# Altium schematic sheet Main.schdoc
size 314 x 206 mm
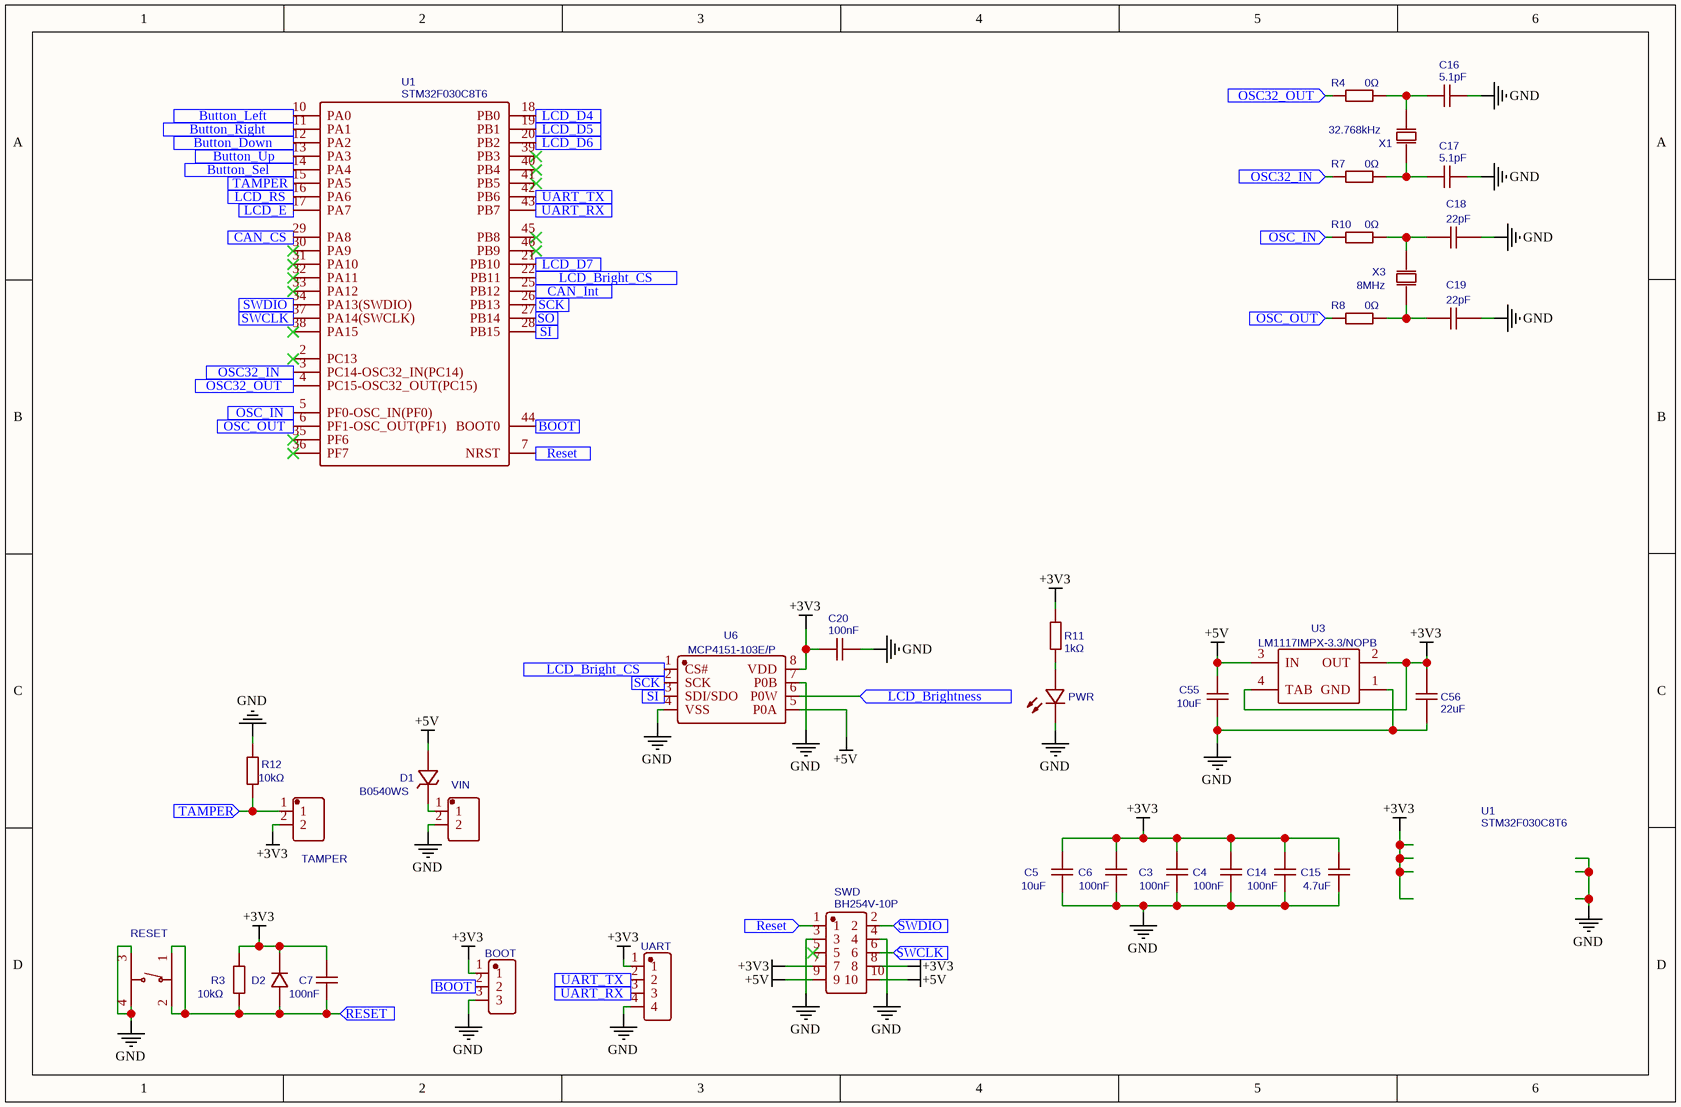
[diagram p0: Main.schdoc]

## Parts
(Parts that share a designator on the sheet are numbered #1, #2 ... from top to bottom, then left to right.)
BOOT  PZ254V-11-03P_C2937625  [HDR-TH_3P-P2.54-V-M]  (value not drawn)
C3  100nF  [C0603]
C4  100nF  [C0603]
C5  10uF  [C0603]
C6  100nF  [C0603]
C7  100nF  [C0603]
C14  100nF  [C0603]
C15  4.7uF  [C0603]
C16  5.1pF  [C0603]
C17  5.1pF  [C0603]
C18  22pF  [C0603]
C19  22pF  [C0603]
C20  100nF  [C0603]
C55  10uF  [C0603]
C56  22uF  [C0603]
D1  B0540WS  [SOD-323_L1.7-W1.3-LS2.6-RD-1]
D2  1N914BWS  [SOD-323_L1.8-W1.3-LS2.5-RD]  (value not drawn)
PWR  FC-1608GHK-570A08  [LED0603-R-RD]  (value not drawn)
R3  10kΩ  [R0603]
R4  0Ω  [R0603]
R7  0Ω  [R0603]
R8  0Ω  [R0603]
R10  0Ω  [R0603]
R11  1kΩ  [R0603]
R12  10kΩ  [R0603]
RESET  TS-1187A-B-A-B  [SW-SMD_4P-L5.1-W5.1-P3.70-LS6.5-TL-2]  (value not drawn)
SWD  BH254V-10P  [IDC-TH_10P-P2.54-V-R2-C5-S2.54]
TAMPER  WJ15EDGRC-3.81-2P  [CONN-TH_2P-P3.81_WJ15EDGRC-3.81-2P]  (value not drawn)
U1#1  STM32F030C8T6  [LQFP-48_L7.0-W7.0-P0.50-LS9.0-BL]
U1#2  STM32F030C8T6  [LQFP-48_L7.0-W7.0-P0.50-LS9.0-BL]
U3  LM1117IMPX-3.3/NOPB  [SOT-223_L6.5-W3.5-P2.30-LS7.0-BR]
U6  MCP4151-103E/P  [PDIP-8_L9.3-W6.4-P2.54-LS7.6-BL]
UART  PZ254V-11-04P_C2691448  [HDR-TH_4P-P2.54-V-M]  (value not drawn)
VIN  WJ15EDGRC-3.81-2P  [CONN-TH_2P-P3.81_WJ15EDGRC-3.81-2P]  (value not drawn)
X1  32.768kHz  [OSC-SMD_L3.2-W1.5]
X3  8MHz  [OSC-TH_L10.0-W4.5-P5.00]

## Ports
BOOT (in), Button_Down (in), Button_Left (in), Button_Right (in), Button_Sel (in), Button_Up (in), CAN_CS (in), CAN_Int (in), LCD_Bright_CS (in), LCD_Brightness (in), LCD_D4 (in), LCD_D5 (in), LCD_D6 (in), LCD_D7 (in), LCD_E (in), LCD_RS (in), OSC32_IN (in), OSC32_OUT (in), OSC_IN (in), OSC_OUT (in), Reset (in), RESET (in), SCK (in), SI (in), SO (in), SWCLK (in), SWDIO (in), TAMPER (in), UART_RX (in), UART_TX (in)

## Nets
+3V3: BOOT.1 C3.2 C4.2 C5.2 C6.2 C7.1 C14.2 C15.1 C20.2 C56.2 D2.1(C) R3.1 R11.2 SWD.7 SWD.8 TAMPER.2 U3.2(OUT) U3.4(TAB) U6.8(VDD) UART.1
+5V: C55.1 D1.2(A) SWD.9 SWD.10 U3.3(IN) U6.5(P0A)
GND: BOOT.3 C3.1 C4.1 C5.1 C6.1 C14.1 C15.2 C16.2 C17.2 C18.1 C19.1 C20.1 C55.2 C56.1 PWR.2(-) R12.2 RESET.3(C) RESET.4(D) SWD.3 SWD.4 U3.1(GND) U6.4(VSS) U6.7(P0B) UART.4 VIN.2
BOOT: BOOT.2 U1#1.44(BOOT0) ; port BOOT
Button_Down: U1#1.12(PA2) ; port Button_Down
Button_Left: U1#1.10(PA0) ; port Button_Left
Button_Right: U1#1.11(PA1) ; port Button_Right
Button_Sel: U1#1.14(PA4) ; port Button_Sel
Button_Up: U1#1.13(PA3) ; port Button_Up
CAN_CS: U1#1.29(PA8) ; port CAN_CS
CAN_Int: U1#1.25(PB12) ; port CAN_Int
LCD_Bright_CS: U1#1.22(PB11) U6.1(CS#) ; port LCD_Bright_CS
LCD_Brightness: U6.6(P0W) ; port LCD_Brightness
LCD_D4: U1#1.18(PB0) ; port LCD_D4
LCD_D5: U1#1.19(PB1) ; port LCD_D5
LCD_D6: U1#1.20(PB2) ; port LCD_D6
LCD_D7: U1#1.21(PB10) ; port LCD_D7
LCD_E: U1#1.17(PA7) ; port LCD_E
LCD_RS: U1#1.16(PA6) ; port LCD_RS
OSC32_IN: R7.1 U1#1.3(PC14-OSC32_IN(PC14)) ; port OSC32_IN
OSC32_OUT: R4.1 U1#1.4(PC15-OSC32_OUT(PC15)) ; port OSC32_OUT
OSC_IN: R10.1 U1#1.5(PF0-OSC_IN(PF0)) ; port OSC_IN
OSC_OUT: R8.1 U1#1.6(PF1-OSC_OUT(PF1)) ; port OSC_OUT
Reset: C7.2 D2.2(A) R3.2 RESET.1(A) RESET.2(B) SWD.1 U1#1.7(NRST) ; port Reset, port RESET
SCK: U1#1.26(PB13) U6.2(SCK) ; port SCK
SI: U1#1.28(PB15) U6.3(SDI/SDO) ; port SI
SO: U1#1.27(PB14) ; port SO
SWCLK: SWD.6 U1#1.37(PA14(SWCLK)) ; port SWCLK
SWDIO: SWD.2 U1#1.34(PA13(SWDIO)) ; port SWDIO
TAMPER: R12.1 TAMPER.1 U1#1.15(PA5) ; port TAMPER
UART_RX: U1#1.43(PB7) UART.3 ; port UART_RX
UART_TX: U1#1.42(PB6) UART.2 ; port UART_TX
NetC16_1: C16.1 R4.2 X1.2(OSC2)
NetC17_1: C17.1 R7.2 X1.1(OSC1)
NetC18_2: C18.2 R10.2 X3.1(OSC1)
NetC19_2: C19.2 R8.2 X3.2(OSC2)
NetD1_1: D1.1(K) VIN.1
NetPWR_1: PWR.1(+) R11.1

Not connected (* = marked no-connect by the designer): SWD 5*; U1#1 2(PC13)* 30(PA9)* 31(PA10)* 32(PA11)* 33(PA12)* 35(PF6)* 36(PF7)* 38(PA15)* 39(PB3)* 40(PB4)* 41(PB5)* 45(PB8)* 46(PB9)*

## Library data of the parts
BOOT = PZ254V-11-03P_C2937625: BOM_Manufacturer: XFCN(台湾兴飞); Contributor: LCSC
C3 C4 C6 C7 C14 C20 = 100nF: BOM_Manufacturer: Prosperity Dielectrics; BOM_Manufacturer Part: FN18X104K500PBG; nameAlias: Capacitance; Contributor: LCSC
C5 C55 = 10uF: BOM_Manufacturer: TAIYO YUDEN; BOM_Manufacturer Part: JMK107BJ106MA-T; nameAlias: Capacitance
C15 = 4.7uF: BOM_Manufacturer: TAIYO YUDEN; BOM_Manufacturer Part: EMK107ABJ475KA-T; nameAlias: Capacitance
C16 C17 = 5.1pF: BOM_Manufacturer: FH; BOM_Manufacturer Part: 0603CG5R1C500NT; nameAlias: Capacitance
C18 C19 = 22pF: BOM_Manufacturer: TDK; BOM_Manufacturer Part: CGA3E2C0G1H220JT0Y0N; nameAlias: Capacitance; Contributor: LCSC
C56 = 22uF: BOM_Manufacturer: MuRata; BOM_Manufacturer Part: GRM188R61A226ME15D; nameAlias: Capacitance
D1 = B0540WS: BOM_Manufacturer: CJ（江苏长电/长晶）; Contributor: LCSC
D2 = 1N914BWS: BOM_Manufacturer: ON Semicon; Contributor: LCSC
PWR = FC-1608GHK-570A08: BOM_Manufacturer: Foshan NationStar Optoelectronics; Contributor: LCSC
R3 = 10kΩ: BOM_Manufacturer: TA-I Tech; BOM_Manufacturer Part: RMS06FT1002; Resistance (Ohms): 10K; nameAlias: Resistance; Contributor: LCSC
R4 R7 R8 R10 = 0Ω: BOM_Manufacturer: PANASONIC; BOM_Manufacturer Part: ERJ-3GEY0R00V; nameAlias: Resistance; Resistance (Ohms): 0
R11 = 1kΩ: BOM_Manufacturer: Ever Ohms Tech; BOM_Manufacturer Part: TR0603B1KP0525; Resistance (Ohms): 1K; nameAlias: Resistance; Contributor: LCSC
R12 = 10kΩ: BOM_Manufacturer: PANASONIC; BOM_Manufacturer Part: ERJ3GEYJ103V; Resistance (Ohms): 10K; nameAlias: Resistance; Contributor: LCSC
RESET = TS-1187A-B-A-B: BOM_Manufacturer: XKB Enterprise; Contributor: LCSC
SWD = BH254V-10P: BOM_Manufacturer: XFCN; Contributor: LCSC
TAMPER VIN = WJ15EDGRC-3.81-2P: BOM_Manufacturer: ReliaPro
U1#1 U1#2 = STM32F030C8T6: BOM_Manufacturer: ST; subpart_no: 1; tags: STM32
U3 = LM1117IMPX-3.3/NOPB: BOM_Manufacturer: TI
U6 = MCP4151-103E/P: BOM_Manufacturer: MICROCHIP(美国微芯); Contributor: lcsc
UART = PZ254V-11-04P_C2691448: BOM_Manufacturer: XFCN(台湾兴飞); Contributor: LCSC
X1 = 32.768kHz: BOM_Manufacturer: Nihon Dempa Kogyo; BOM_Manufacturer Part: NX3215SA-32.768KHZ(STD-MUA-8); nameAlias: Frequency; Contributor: LCSC
X3 = 8MHz: BOM_Manufacturer: YXC; BOM_Manufacturer Part: X49SD8MSD2SC; nameAlias: Frequency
